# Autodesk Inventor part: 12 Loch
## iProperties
Created: 2009-02
Part Number: 12 Loch
Document SubType Name: Modeling
Designer: matthias.steiner
Density: 1 g/cm^3
Author: matthias.steiner
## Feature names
1. Extrusion1
2. Bohrung1 [Hole]
3. Runde Anordnung1 [Circular Pattern]
